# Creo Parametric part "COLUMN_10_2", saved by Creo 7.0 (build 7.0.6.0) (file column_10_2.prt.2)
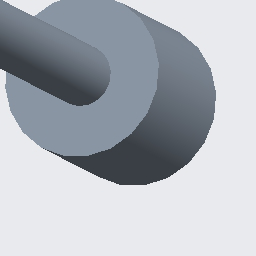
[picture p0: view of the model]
Units: millimeter Newton Second (mmNs); MM, TONNE, SECS

Created from: XX_MMNS_PART_SOLID_ABS.PRT

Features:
  1. datum plane "RIGHT"
  2. datum plane "TOP"
  3. datum plane "FRONT"
  4. coordinate system
  5. extrusion "Extrude 1"
  6. extruded cut "Extrude 2"
  7. extrusion "Extrude 3"

Surfaces: 4 plane, 3 cylinder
